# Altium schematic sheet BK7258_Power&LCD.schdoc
size 289 x 189 mm
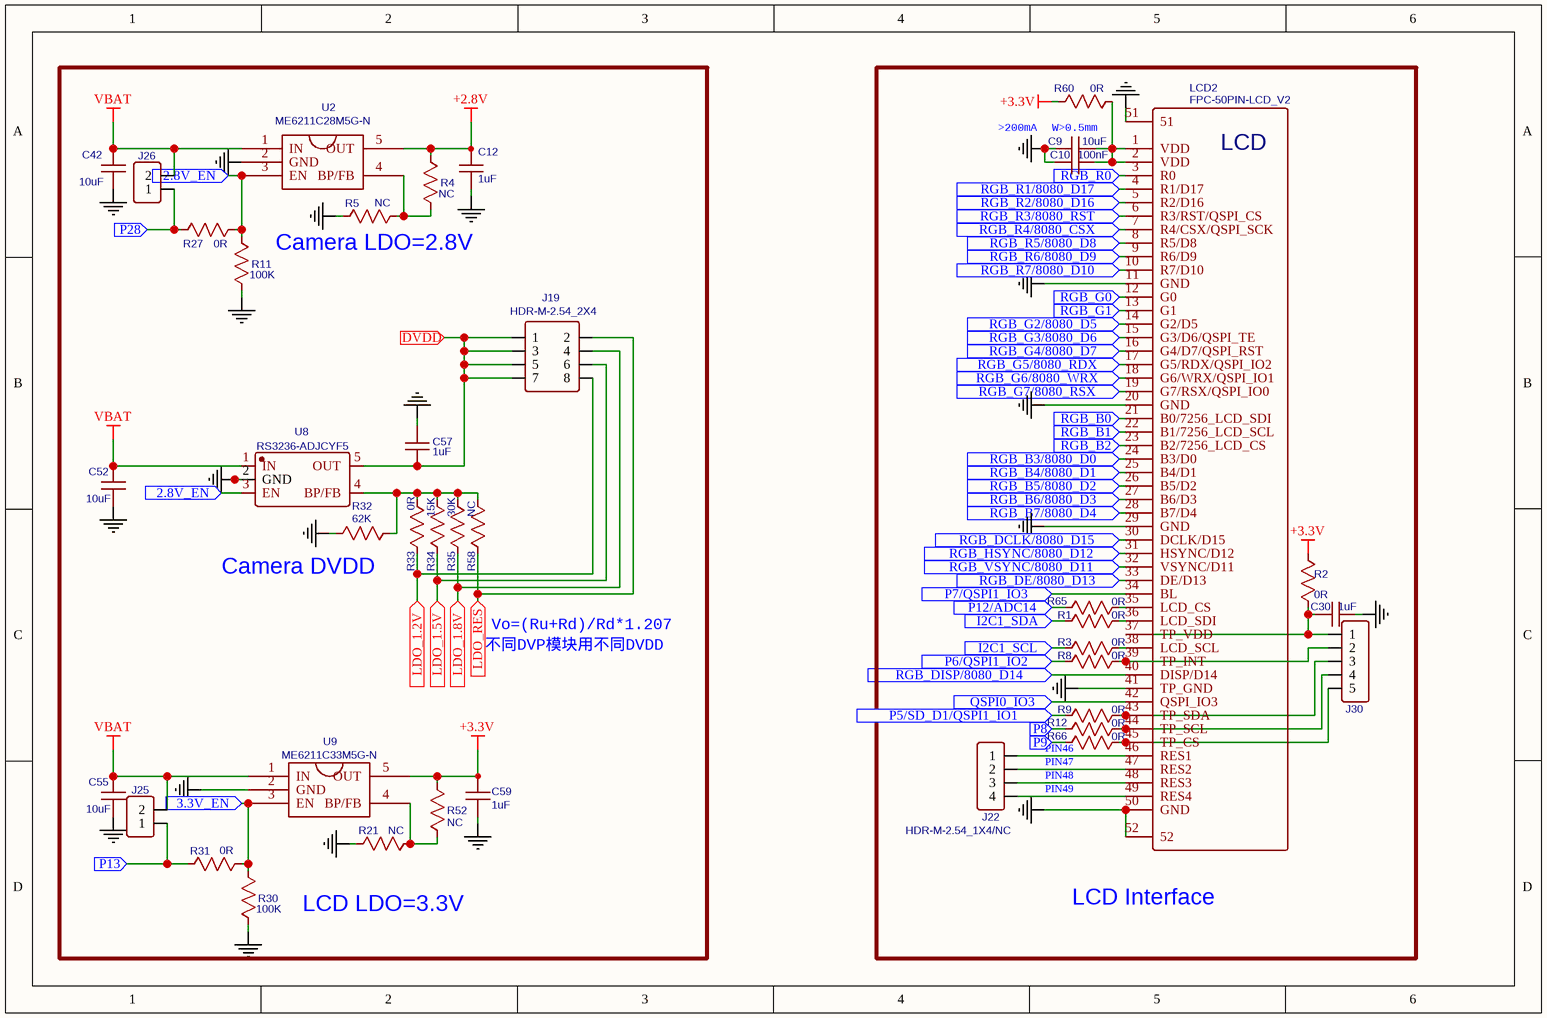
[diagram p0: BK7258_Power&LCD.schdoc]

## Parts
C9  10uF  [C0603]
C10  100nF  [C0402]
C12  1uF  [C0402]
C30  1uF  [C0402]
C42  10uF  [C0603]
C52  10uF  [C0603]
C55  10uF  [C0603]
C57  1uF  [C0402]
C59  1uF  [C0402]
J19  HDR-M-2.54_2X4  [HDR-M-2.54_2X4]
J22  HDR-M-2.54_1X4/NC  [HDR-M-2.54_1X4]
J25  HDR-M-2.54_1x2  [HDR-M-2.54_1X2]  (value not drawn)
J26  HDR-M-2.54_1x2  [HDR-M-2.54_1X2]  (value not drawn)
J30  HDR-M-2.54_1x5  [HDR-M-2.54_1X5]  (value not drawn)
LCD2  FPC-50PIN-LCD_V2  [FPC-SMD_AFC01-S50FCC-00]
R1  0R  [R0201]
R2  0R  [R0201]
R3  0R  [R0201]
R4  NC  [R0402]
R5  NC  [R0402]
R8  0R  [R0201]
R9  0R  [R0201]
R11  100K  [R0402]
R12  0R  [R0201]
R21  NC  [R0402]
R27  0R  [R0402]
R30  100K  [R0402]
R31  0R  [R0402]
R32  62K  [R0402]
R33  0R  [R0402]
R34  15K  [R0402]
R35  30K  [R0402]
R52  NC  [R0402]
R58  NC  [R0402]
R60  0R  [R0402]
R65  0R  [R0201]
R66  0R  [R0201]
U2  ME6211C28M5G-N  [SOT23-5_SGM2019]
U8  RS3236-ADJCYF5  [SOT23-5_SGM2019]
U9  ME6211C33M5G-N  [SOT23-5_SGM2019]

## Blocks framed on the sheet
LCD Interface: C9 C10 C30 J22 J30 LCD2 R1-R3 R8 R9 R12 R60 R65 R66

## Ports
2.8V_EN (in), 3.3V_EN (in), DVDD (in), I2C1_SCL (in), I2C1_SDA (in), LDO_1.2V (in), LDO_1.5V (in), LDO_1.8V (in), LDO_RES (in), P5/SD_D1/QSPI1_IO1 (in), P6/QSPI1_IO2 (in), P7/QSPI1_IO3 (in), P8 (in), P9 (in), P12/ADC14 (in), P13 (in), P28 (in), QSPI0_IO3 (in), RGB_B0 (in), RGB_B1 (in), RGB_B2 (in), RGB_B3/8080_D0 (in), RGB_B4/8080_D1 (in), RGB_B5/8080_D2 (in), RGB_B6/8080_D3 (in), RGB_B7/8080_D4 (in), RGB_DCLK/8080_D15 (in), RGB_DE/8080_D13 (in), RGB_DISP/8080_D14 (in), RGB_G0 (in), RGB_G1 (in), RGB_G2/8080_D5 (in), RGB_G3/8080_D6 (in), RGB_G4/8080_D7 (in), RGB_G5/8080_RDX (in), RGB_G6/8080_WRX (in), RGB_G7/8080_RSX (in), RGB_HSYNC/8080_D12 (in), RGB_R0 (in), RGB_R1/8080_D17 (in), RGB_R2/8080_D16 (in), RGB_R3/8080_RST (in), RGB_R4/8080_CSX (in), RGB_R5/8080_D8 (in), RGB_R6/8080_D9 (in), RGB_R7/8080_D10 (in), RGB_VSYNC/8080_D11 (in)

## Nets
+2.8V: C12.1 R4.1 U2.5(OUT)
+3.3V: C59.1 R2.2 R52.1 R60.1 U9.5(OUT)
GGND: C9.1 C10.2 C12.2 C30.1 C42.2 C52.2 C55.2 C57.2 C59.2 LCD2.11(GND) LCD2.20(GND) LCD2.29(GND) LCD2.41(TP_GND) LCD2.50(GND) LCD2.51 LCD2.52 R5.2 R11.2 R21.2 R30.2 R32.2 U2.2(GND) U8.2(GND) U9.2(GND)
VBAT: C42.1 C52.1 C55.1 J25.2 J26.2 U2.1(IN) U8.1(IN) U9.1(IN)
2.8V_EN: R11.1 R27.1 U2.3(EN) U8.3(EN) ; port 2.8V_EN
3.3V_EN: R30.1 R31.1 U9.3(EN) ; port 3.3V_EN
DVDD: C57.1 J19.1 J19.3 J19.5 J19.7 U8.5(OUT) ; port DVDD
I2C1_SCL: R3.1 ; port I2C1_SCL
I2C1_SDA: R1.1 ; port I2C1_SDA
LDO_1.2V: J19.8 R33.2 ; port LDO_1.2V
LDO_1.5V: J19.6 R34.2 ; port LDO_1.5V
LDO_1.8V: J19.4 R35.2 ; port LDO_1.8V
LDO_RES: J19.2 R58.2 ; port LDO_RES
P5/SD_D1/QSPI1_IO1: R9.1 ; port P5/SD_D1/QSPI1_IO1
P6/QSPI1_IO2: R8.1 ; port P6/QSPI1_IO2
P7/QSPI1_IO3: LCD2.34(BL) ; port P7/QSPI1_IO3
P8: R12.1 ; port P8
P9: R66.1 ; port P9
P12/ADC14: R65.1 ; port P12/ADC14
P13: J25.1 R31.2 ; port P13
P28: J26.1 R27.2 ; port P28
PIN46: J22.1 LCD2.46(RES1)
PIN47: J22.2 LCD2.47(RES2)
PIN48: J22.3 LCD2.48(RES3)
PIN49: J22.4 LCD2.49(RES4)
QSPI0_IO3: LCD2.42(QSPI_IO3) ; port QSPI0_IO3
RGB_B0: LCD2.21(B0/7256_LCD_SDI) ; port RGB_B0
RGB_B1: LCD2.22(B1/7256_LCD_SCL) ; port RGB_B1
RGB_B2: LCD2.23(B2/7256_LCD_CS) ; port RGB_B2
RGB_B3/8080_D0: LCD2.24(B3/D0) ; port RGB_B3/8080_D0
RGB_B4/8080_D1: LCD2.25(B4/D1) ; port RGB_B4/8080_D1
RGB_B5/8080_D2: LCD2.26(B5/D2) ; port RGB_B5/8080_D2
RGB_B6/8080_D3: LCD2.27(B6/D3) ; port RGB_B6/8080_D3
RGB_B7/8080_D4: LCD2.28(B7/D4) ; port RGB_B7/8080_D4
RGB_DCLK/8080_D15: LCD2.30(DCLK/D15) ; port RGB_DCLK/8080_D15
RGB_DE/8080_D13: LCD2.33(DE/D13) ; port RGB_DE/8080_D13
RGB_DISP/8080_D14: LCD2.40(DISP/D14) ; port RGB_DISP/8080_D14
RGB_G0: LCD2.12(G0) ; port RGB_G0
RGB_G1: LCD2.13(G1) ; port RGB_G1
RGB_G2/8080_D5: LCD2.14(G2/D5) ; port RGB_G2/8080_D5
RGB_G3/8080_D6: LCD2.15(G3/D6/QSPI_TE) ; port RGB_G3/8080_D6
RGB_G4/8080_D7: LCD2.16(G4/D7/QSPI_RST) ; port RGB_G4/8080_D7
RGB_G5/8080_RDX: LCD2.17(G5/RDX/QSPI_IO2) ; port RGB_G5/8080_RDX
RGB_G6/8080_WRX: LCD2.18(G6/WRX/QSPI_IO1) ; port RGB_G6/8080_WRX
RGB_G7/8080_RSX: LCD2.19(G7/RSX/QSPI_IO0) ; port RGB_G7/8080_RSX
RGB_HSYNC/8080_D12: LCD2.31(HSYNC/D12) ; port RGB_HSYNC/8080_D12
RGB_R0: LCD2.3(R0) ; port RGB_R0
RGB_R1/8080_D17: LCD2.4(R1/D17) ; port RGB_R1/8080_D17
RGB_R2/8080_D16: LCD2.5(R2/D16) ; port RGB_R2/8080_D16
RGB_R3/8080_RST: LCD2.6(R3/RST/QSPI_CS) ; port RGB_R3/8080_RST
RGB_R4/8080_CSX: LCD2.7(R4/CSX/QSPI_SCK) ; port RGB_R4/8080_CSX
RGB_R5/8080_D8: LCD2.8(R5/D8) ; port RGB_R5/8080_D8
RGB_R6/8080_D9: LCD2.9(R6/D9) ; port RGB_R6/8080_D9
RGB_R7/8080_D10: LCD2.10(R7/D10) ; port RGB_R7/8080_D10
RGB_VSYNC/8080_D11: LCD2.32(VSYNC/D11) ; port RGB_VSYNC/8080_D11
NetC9_2: C9.2 C10.1 LCD2.1(VDD) LCD2.2(VDD) R60.2
NetC30_2: C30.2 J30.1 LCD2.37(TP_VDD) R2.1
NetJ30_2: J30.2 LCD2.39(TP_INT) R8.2
NetJ30_3: J30.3 LCD2.43(TP_SDA) R9.2
NetJ30_4: J30.4 LCD2.44(TP_SCL) R12.2
NetJ30_5: J30.5 LCD2.45(TP_CS) R66.2
NetLCD2_35: LCD2.35(LCD_CS) R65.2
NetLCD2_36: LCD2.36(LCD_SDI) R1.2
NetLCD2_38: LCD2.38(LCD_SCL) R3.2
NetR4_2: R4.2 R5.1 U2.4(BP/FB)
NetR21_1: R21.1 R52.2 U9.4(BP/FB)
NetR32_1: R32.1 R33.1 R34.1 R35.1 R58.1 U8.4(BP/FB)

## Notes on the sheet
- >200mA
- W>0.5mm
- (near R5) Camera LDO=2.8V
- (near R32) Camera DVDD
- Vo=(Ru+Rd)/Rd*1.207
- 不同DVP模块用不同DVDD
- LCD LDO=3.3V

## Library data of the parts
C9 C42 C52 C55 = 10uF: Manufacturer Part Number: 06035A101KAT2A; Manufacturer: AVX; APN: C029-0
C10 = 100nF: Manufacturer: AVX; Manufacturer Part Number: 06035C103KAt2A; APN: C006-0
C12 C30 C57 C59 = 1uF: Manufacturer: AVX; Manufacturer Part Number: 06035C103KAt2A; APN: C006-0
J19 = HDR-M-2.54_2X4: Contributor: LCEDA_Lib
J22 = HDR-M-2.54_1X4/NC: Contributor: LCEDA_Lib
J25 J26 = HDR-M-2.54_1x2: Contributor: LCEDA_Lib
J30 = HDR-M-2.54_1x5: Contributor: LCEDA_Lib
LCD2 = FPC-50PIN-LCD_V2: Manufacturer: JS(钜硕电子); Manufacturer Part: AFC01-S50FCC-00; Contributor: qunshan.xu
R1-R3 R8 R9 R12 R27 R31 R33 R60 R65 R66 = 0R: nameAlias: Value(Ω); Contributor: LCEDA_Lib
R4 R5 R21 R52 R58 = NC: nameAlias: Value(Ω); Contributor: LCEDA_Lib
R11 R30 = 100K: nameAlias: Value(Ω); Contributor: LCEDA_Lib
R32 = 62K: nameAlias: Value(Ω); Contributor: LCEDA_Lib
R34 = 15K: nameAlias: Value(Ω); Contributor: LCEDA_Lib
R35 = 30K: nameAlias: Value(Ω); Contributor: LCEDA_Lib
U2 = ME6211C28M5G-N: BOM_Manufacturer: MICRONE(南京微盟)
U8 = RS3236-ADJCYF5: Manufacturer: RUNIC(润石); Contributor: LCSC
U9 = ME6211C33M5G-N: BOM_Manufacturer: MICRONE(南京微盟)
